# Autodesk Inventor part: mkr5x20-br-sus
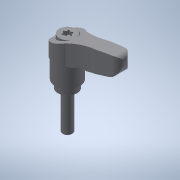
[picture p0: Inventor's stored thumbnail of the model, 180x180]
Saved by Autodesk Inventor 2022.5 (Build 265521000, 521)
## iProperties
Created: 2017-09
Part Number: mkr5x20-br-sus
Material: 一般
Document SubType Name: Modeling
Designer: imaocorp
Density: 1 g/cm^3
Appearance: 既定
Author: imaocorp
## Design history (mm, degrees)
node "mkr5x20-br-sus.x_t1"
node "mkr5x20-br-sus"
node "Base1"
